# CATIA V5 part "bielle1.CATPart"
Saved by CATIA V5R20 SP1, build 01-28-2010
Part number: bielle57
Bounding box of the stored display mesh (mm): x 30.5 to 87, y -5 to 9, z 28.093 to 41.907
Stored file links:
  E:\EDELI\gcausse\Edeli_2012_613_gcausse\bielle1.CATPart
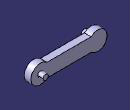
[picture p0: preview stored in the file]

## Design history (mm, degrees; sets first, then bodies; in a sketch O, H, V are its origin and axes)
Parameters
  long = 0.0425
  diamtrou = 0.005
Set1 "point"
  DatumSurface1
  DatumCurve1
  Sketch1 on end face of Pad1, origin (0, 5, 0), H (-1, 0, 0), V (0, 0, 1)
    circle A1 centre (-80, 35) radius 2
    reference projected arc E1 centre (-80, 35) radius 7 from (-75.101, 40) to (-75.101, 30) ccw from edge [face of Pad1 from Sketch2.A2 | end face of Pad1]
    radius A1 = 2
    concentricity: A1 E1
Body1 (main body)
  Sketch2 on zx-plane, origin (0, 0, 0), H (-1, 0, 0), V (0, 0, 1)
    line L1 (-42.399, 40) -> (-75.101, 40)
    line L2 (-42.399, 30) -> (-75.101, 30)
    arc A1 centre (-37.5, 35) radius 7 from (-42.399, 40) to (-42.399, 30) cw
    point P5 (-37.5, 35)
    point P6 (-32.601, 30)
    arc A2 centre (-80, 35) radius 7 from (-75.101, 40) to (-75.101, 30) ccw
    point P7 (-80, 35)
    circle A3 centre (-37.5, 35) radius 2.5
    distance P7 L1 = 5
    distance P5 L2 = 5
    distance L2 L1 = 10
    radius A1 = 7
    radius A2 = 7
    distance P5 P7 = 42.5 {= long}
    radius A3 = 2.5
    horizontal: L1 H, L2 H
    coincidence: A1 P6, P6 L2
  Pad1: profile Sketch2, direction (0, 1, 0), length 5
  Pad2: profile Sketch1, direction (0, 1, 0), length 4
  Sketch3 on end face of Pad1, origin (0, 5, 0), H (-1, 0, 0), V (0, 0, 1)
    circle A1 centre (-37.5, 35) radius 2.5
    reference projected arc E1 centre (-37.5, 35) radius 7 from (-42.399, 30) to (-42.399, 40) ccw from edge [face of Pad1 from Sketch2.A1 | end face of Pad1]
    radius A1 = 2.5
    concentricity: A1 E1
  Pad3: profile Sketch3, direction (0, -1, 0), length 10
